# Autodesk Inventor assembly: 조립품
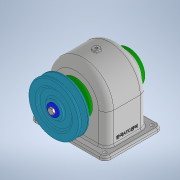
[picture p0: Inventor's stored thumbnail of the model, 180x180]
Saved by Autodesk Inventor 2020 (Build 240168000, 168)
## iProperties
Created: 2022-09
Part Number: 조립품
Document SubType Name: Assembly
Designer: Administrator
Author: Administrator
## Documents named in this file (16)
- C:\Users\Administrator\Desktop\720906V1016\조립품.iam
- C:\Users\Administrator\Desktop\720906V1016\본체.ipt
- C:\Users\Administrator\Desktop\720906V1016\뒤커버.ipt
- C:\Users\Administrator\Desktop\720906V1016\앞커버.ipt
- C:\Users\Administrator\Desktop\720906V1016\축.ipt
- C:\Users\Administrator\Desktop\720906V1016\베어링 6203.ipt
- C:\Users\Administrator\Desktop\720906V1016\스퍼기어.ipt
- C:\Users\Administrator\Desktop\720906V1016\키 5 x 5 x 18.ipt
- C:\Users\Administrator\Desktop\720906V1016\키 6 x 6 x 22.ipt
- C:\Users\Administrator\Desktop\720906V1016\V-벨트풀리.ipt
- C:\Users\Administrator\Desktop\720906V1016\멈춤나사 M4 x 10.ipt
- C:\Users\Administrator\Desktop\720906V1016\볼트 M3 x 10.ipt
- C:\Users\Administrator\Desktop\720906V1016\오일 실 17 x 30 x 8.ipt
- C:\Users\Administrator\Desktop\720906V1016\와셔 6 x 22.ipt
- C:\Users\Administrator\Desktop\720906V1016\육각머리볼트 M3 x 8.ipt
- C:\Users\Administrator\Desktop\720906V1016\칼라.ipt
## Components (9 placed, 2 different names)
1. V-벨트풀리:1
2. ISO 4762 M3 x 10:1
3. ISO 4762 M3 x 10:2
4. ISO 4762 M3 x 10:3
5. ISO 4762 M3 x 10:4
6. ISO 4762 M3 x 10:5
7. ISO 4762 M3 x 10:6
8. ISO 4762 M3 x 10:7
9. ISO 4762 M3 x 10:8
